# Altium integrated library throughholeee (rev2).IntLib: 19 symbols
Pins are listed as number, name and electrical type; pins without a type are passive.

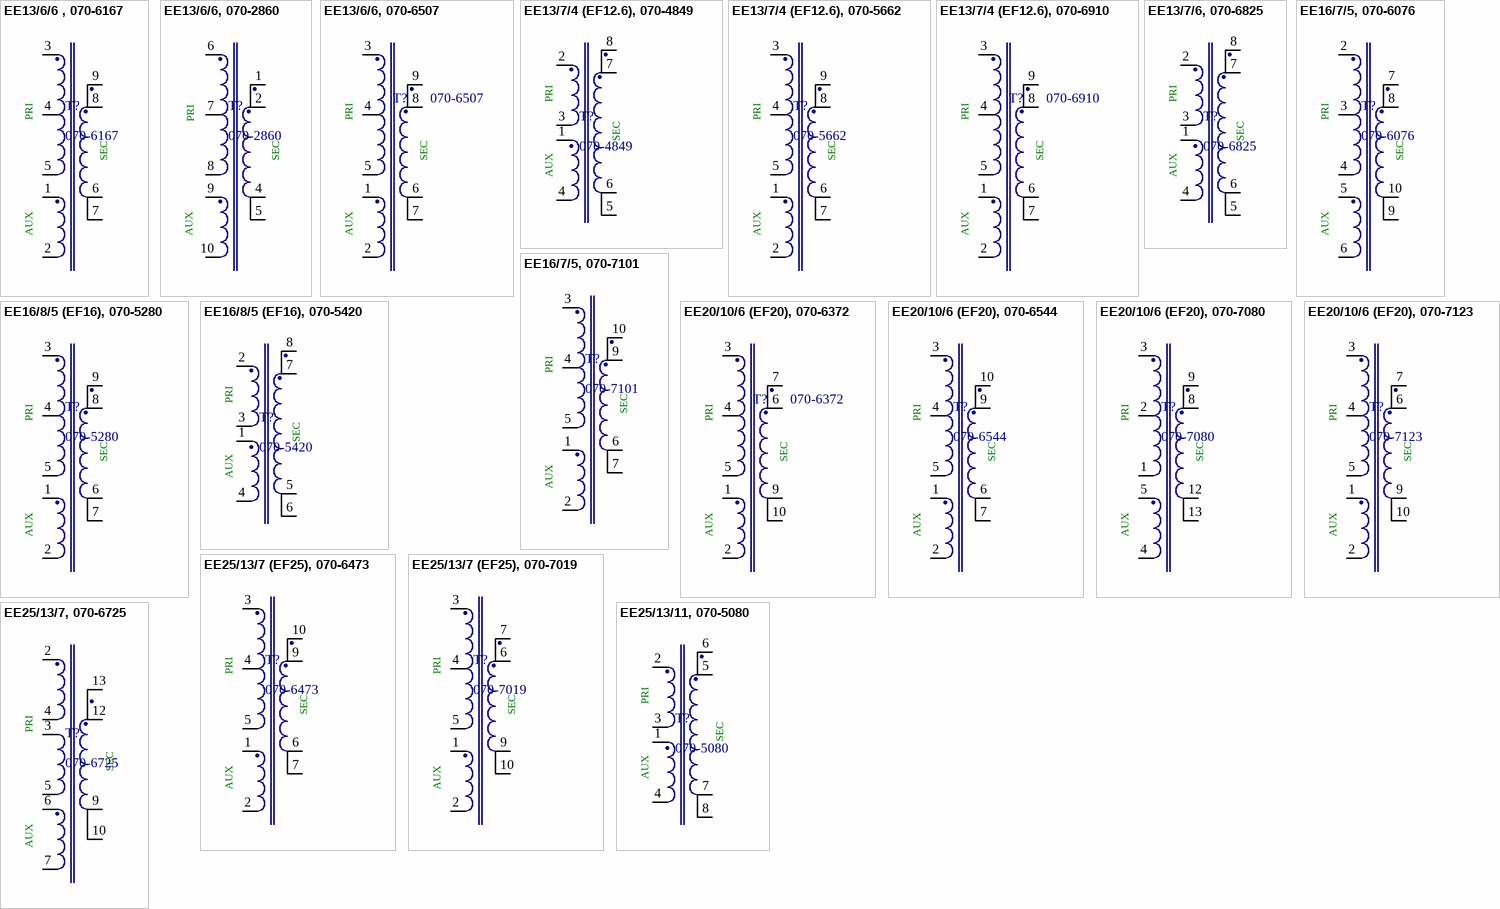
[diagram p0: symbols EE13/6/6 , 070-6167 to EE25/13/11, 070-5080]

## EE13/6/6 , 070-6167
designator T?, comment 070-6167
Transformer 9-Terminal EXT, THT, Horizontal, EE Style , EE13/6/6; Manufacturer: Würth Elektronik Midcom; Core: 150-1994
footprint EE13-6-6_6167 (THT, Body 20.45x13.72mm, 9Pins,Pitch 2.72mm)
pins: 1, 2, 3, 4, 5, 6, 7, 8, 9

## EE13/6/6, 070-2860
designator T?, comment 070-2860
Transformer 10-Terminal, THT, Vertical, EE Style Bobbins, EE13/6/6; Manufacturer: Würth Elektronik Midcom; Core: 150-1994
footprint EE13-6-6_2860 (THT, Body 14.73X14.73mm, 10Pins,Pitch 2.50mm)
pins: 1, 2, 4, 5, 6, 7, 8, 9, 10

## EE13/6/6, 070-6507
designator T?, comment 070-6507
EE13/6/6 9-Term. EXT, THT, Horizontal; Manufacturer: Wurth Elektronik; Core: 150-1994
footprint EE13-6-6_6507 (EE13/6/6 9-Term. EXT, THT, Horizontal)
pins: 1, 2, 3, 4, 5, 6, 7, 8, 9

## EE13/7/4 (EF12.6), 070-4849
designator T?, comment 070-4849
Transformer 8-Terminal , THT, Horizontal, EE Style Bobbins, EE13/7/4 (EF12.6); Manufacturer: Würth Elektronik Midcom; Core: 150-2300
footprint EE13-7-4_4849
pins: 1, 2, 3, 4, 5, 6, 7, 8

## EE13/7/4 (EF12.6), 070-5662
designator T?, comment 070-5662
Transformer 9-Terminal EXT, THT, Horizontal, EE Style Bobbins, EE13/7/4 (EF12.6); Manufacturer: Würth Elektronik Midcom; Core: 150-2300
footprint EE13-7-4_5662 (THT, Body 20.45x13.72mm, 9Pins,Pitch 2.72mm)
pins: 1, 2, 3, 4, 5, 6, 7, 8, 9

## EE13/7/4 (EF12.6), 070-6910
designator T?, comment 070-6910
EE13/7/4 (EF12.6) 9-Term. EXT, THT, Horizontal; Manufacturer: Wurth Elektronik; Core: 150-2300
footprint EE13-7-4_6910 (EE13/7/4 (EF12.6) 9-Term. EXT, THT, Horizontal)
pins: 1, 2, 3, 4, 5, 6, 7, 8, 9

## EE13/7/6, 070-6825
designator T?, comment 070-6825
EE13/7/6 TH 8-Term. EXT, THT, Horizontal; Manufacturer: Würth Elektronik Midcom; Core: 150-3045
footprint EE13-7-6_6825 (THT, Body 15X15.75mm, 8Pins,Pitch 3.81mm)
pins: 1, 2, 3, 4, 5, 6, 7, 8

## EE16/7/5, 070-6076
designator T?, comment 070-6076
EE16/7/5 10-Term. EXT, THT, Vertical; Manufacturer: Würth Elektronik Midcom; Core: 150-2115
footprint EE16-7-5_6076 (THT, Body 18.50x16.50mm, 10Pins,Pitch 2.70mm)
pins: 2, 3, 4, 5, 6, 7, 8, 9, 10

## EE16/7/5, 070-7101
designator T?, comment 070-7101
EE16/7/5 10-Term. EXT, THT, Horizontal; Manufacturer: Würth Elektronik Midcom; Core: 150-2115
footprint EE16-7-5_7101 (THT, Body 20x17.50mm, 10Pins,Pitch 3.20mm)
pins: 1, 2, 3, 4, 5, 6, 7, 9, 10

## EE16/8/5 (EF16), 070-5280
designator T?, comment 070-5280
Transformer 9-Terminal EXT, THT, Horizontal, EE Style Bobbins, EE16/8/5 (EF16); Manufacturer: Würth Elektronik Midcom; Core: 150-2182
footprint EE16-8-5_5280
pins: 1, 2, 3, 4, 5, 6, 7, 8, 9

## EE16/8/5 (EF16), 070-5420
designator T?, comment 070-5420
Transformer 8-Terminal , THT, Horizontal, EE Style Bobbins, EE13/6/6; Manufacturer: Würth Elektronik Midcom; Core: 150-2182
footprint EE16-8-5_5420 (THT, Body 20.30x17.96mm, 8Pins,Pitch 3.80mm)
pins: 1, 2, 3, 4, 5, 6, 7, 8

## EE20/10/6 (EF20), 070-6372
designator T?, comment 070-6372
EE20/10/6 10-Terminal EXT, THT, Vertical; Manufacturer: Wurth Elektronik; Core: 150-1945
footprint EE20-10-6_6372 (EE20/10/6 10-Terminal EXT, THT, Vertical)
pins: 1, 2, 3, 4, 5, 6, 7, 9, 10

## EE20/10/6 (EF20), 070-6544
designator T?, comment 070-6544
EE20/10/6 (EF20) 10-Term., THT, Horizontal; Manufacturer: Würth Elektronik Midcom; Core: 150-1945
footprint EE20-10-6_6544 (THT, Body 23.0x22.0mm, 10Pins,Pitch 3.81mm)
pins: 1, 2, 3, 4, 5, 6, 7, 9, 10

## EE20/10/6 (EF20), 070-7080
designator T?, comment 070-7080
EE20/10/6 (EF20) 14-Term. EXT, THT, Horizontal; Manufacturer: Würth Elektronik Midcom; Core: 150-1945
footprint EE20-10-6_7080 (THT, Body 22.2.0x25.0mm, 14Pins,Pitch 2.49mm)
pins: 1, 2, 3, 4, 5, 8, 9, 12, 13

## EE20/10/6 (EF20), 070-7123
designator T?, comment 070-7123
EE20/10/6 (EF20) 10-Term., THT, Vertical; Manufacturer: Würth Elektronik Midcom; Core: 150-1945
footprint EE20-10-6_7123 (THT, Body 22.25.0x14.4mm, 10Pins,Pitch 3.80mm)
pins: 1, 2, 3, 4, 5, 6, 7, 9, 10

## EE25/13/7 (EF25), 070-6473
designator T?, comment 070-6473
EE25/13/7 (EF25) 10-Term., THT, Horizontal; Manufacturer: Würth Elektronik Midcom; Core: 150-2039
footprint EE25-13-7_6473 (THT, Body 29.21x27.94mm, 10Pins, Pitch 5.08mm)
pins: 1, 2, 3, 4, 5, 6, 7, 9, 10

## EE25/13/7 (EF25), 070-7019
designator T?, comment 070-7019
EE25/13/7 (EF25) 10-Term., THT, Vertical; Manufacturer: Würth Elektronik Midcom; Core: 150-2039
footprint EE25-13-7_7019 (THT, Body 27.95x20.32mm, 10Pins, Pitch 5.00mm)
pins: 1, 2, 3, 4, 5, 6, 7, 9, 10

## EE25/13/7, 070-6725
designator T?, comment 070-6725
Transformer 14-Terminal EXT, THT, Horizontal, EE Style Bobbins, EE25/13/7; Manufacturer: Würth Elektronik Midcom; Core: 150-2039
footprint EE25-13-7_6725 (THT, Body 27.05x32.25mm, 14Pins, Pitch 3.81mm)
pins: 2, 3, 4, 5, 6, 7, 9, 10, 12, 13

## EE25/13/11, 070-5080
designator T?, comment 070-5080
Transformer 8-Terminal, THT, Vertical, EE Style Bobbins, EE25/13/11; Manufacturer: Würth Elektronik Midcom; Core: 150-1680
footprint EE25-13-11_5080 (THT, Body 26.00x23.50mm, 8Pins, Pitch 5.00mm)
pins: 1, 2, 3, 4, 5, 6, 7, 8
